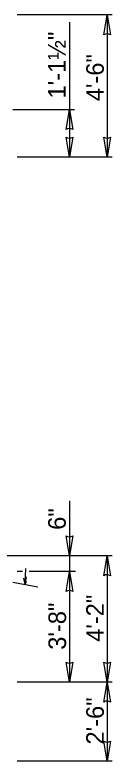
# Model space of a CAD drawing. Extents: x -30 to 76, y -31 to 50.
# Drawn here: x 29.22 to 29.99, y -20.83 to -14.93 of the extents above; entities that cross this region are included whole.
import ezdxf

# ---------------------------------------------------------------- set-up
doc = ezdxf.new("R2010")
doc.units = 0
for name, color, linetype in [('Default', 7, 'Continuous'), ('SH_Data', 7, 'Continuous'), ('XS_P_Finished_Grade', 7, 'Continuous')]:
    doc.layers.add(name, color=color, linetype=linetype)

msp = doc.modelspace()

# ---------------------------------------------------------------- linework, layer by layer
at = {"layer": 'Default'}
for p, q in [((29.9288, -15.0831), (29.9551, -14.9253)), ((29.9551, -14.9253), (29.9815, -15.0836)), ((29.9288, -15.0831), (29.9288, -15.0831)), ((29.9815, -15.0836), (29.9815, -15.0835)), ((29.6288, -15.8331), (29.6551, -15.6753)), ((29.6551, -15.6753), (29.6815, -15.8336)), ((29.6288, -15.8331), (29.6288, -15.8331)), ((29.6815, -15.8336), (29.6815, -15.8335)), ((29.6551, -16.0503), (29.6288, -15.892)), ((29.6288, -15.892), (29.6288, -15.8921)), ((29.6815, -15.8925), (29.6551, -16.0503)), ((29.6815, -15.8925), (29.6815, -15.8925)), ((29.9551, -16.0503), (29.9288, -15.892)), ((29.9288, -15.892), (29.9288, -15.8921)), ((29.9815, -15.8925), (29.9551, -16.0503)), ((29.9815, -15.8925), (29.9815, -15.8925)), ((29.6551, -19.2068), (29.6288, -19.0485)), ((29.6288, -19.0485), (29.6288, -19.0486)), ((29.6815, -19.049), (29.6551, -19.2068)), ((29.6815, -19.049), (29.6815, -19.049)), ((29.9288, -19.3645), (29.9551, -19.2068)), ((29.9551, -19.2068), (29.9815, -19.3651)), ((29.6288, -19.4895), (29.6551, -19.3318)), ((29.6551, -19.3318), (29.6815, -19.4901)), ((29.9288, -19.3645), (29.9288, -19.3645)), ((29.9815, -19.3651), (29.9815, -19.365)), ((29.6288, -19.4895), (29.6288, -19.4895)), ((29.6815, -19.4901), (29.6815, -19.49)), ((29.6551, -20.2068), (29.6288, -20.0486)), ((29.6288, -20.0486), (29.6288, -20.0487)), ((29.6815, -20.0491), (29.6551, -20.2068)), ((29.6815, -20.0491), (29.6815, -20.0491)), ((29.9551, -20.2068), (29.9288, -20.0486)), ((29.9288, -20.0486), (29.9288, -20.0487)), ((29.9815, -20.0491), (29.9551, -20.2068)), ((29.9815, -20.0491), (29.9815, -20.0491)), ((29.9288, -20.3646), (29.9551, -20.2068)), ((29.9551, -20.2068), (29.9815, -20.3651)), ((29.9288, -20.3646), (29.9288, -20.3646)), ((29.9815, -20.3651), (29.9815, -20.365)), ((29.9551, -20.8318), (29.9288, -20.6736)), ((29.9288, -20.6736), (29.9288, -20.6737)), ((29.9815, -20.6741), (29.9551, -20.8318)), ((29.9815, -20.6741), (29.9815, -20.6741))]:
    msp.add_line(p, q, dxfattribs=at)
for centre, start, end in [((29.9547, -15.1234), 56.178, 122.85877), ((29.6547, -15.8734), 56.178, 122.85877), ((29.6555, -15.8522), 236.178, 302.85877), ((29.9555, -15.8522), 236.178, 302.85877), ((29.6555, -19.0087), 236.178, 302.85877), ((29.9547, -19.4049), 56.178, 122.85877), ((29.6547, -19.5299), 56.178, 122.85877), ((29.6555, -20.0088), 236.178, 302.85877), ((29.9555, -20.0088), 236.178, 302.85877), ((29.9547, -20.4049), 56.178, 122.85877), ((29.9555, -20.6338), 236.178, 302.85877)]:
    msp.add_arc(centre, 0.048, start, end, dxfattribs=at)
at = {"layer": 'SH_Data'}
for p, q in [((29.9948, -14.9253), (29.2392, -14.9253)), ((29.9551, -14.9253), (29.9551, -16.0503)), ((29.6551, -14.9833), (29.6551, -15.6753)), ((29.6965, -15.6753), (29.2051, -15.6753)), ((29.6551, -15.6753), (29.6551, -16.0503)), ((29.9948, -16.0503), (29.2392, -16.0503)), ((29.6551, -18.772), (29.6551, -19.2068)), ((29.9948, -19.2068), (28.6646, -19.2068)), ((29.6551, -19.2068), (29.6551, -19.3318)), ((29.9551, -19.2068), (29.9551, -20.2068)), ((29.2833, -19.3318), (29.2392, -19.3318)), ((29.7031, -19.3318), (29.3351, -19.3318)), ((29.6551, -19.3318), (29.6551, -20.2068)), ((29.9948, -20.2068), (29.2392, -20.2068)), ((29.9551, -20.2068), (29.9551, -20.8318)), ((29.9948, -20.8318), (29.2392, -20.8318))]:
    msp.add_line(p, q, dxfattribs=at)
at = {"layer": 'XS_P_Finished_Grade'}
for p, q in [((29.3047, -19.434), (29.3095, -19.3078)), ((29.3047, -19.434), (29.3156, -19.3723)), ((29.2051, -19.4164), (29.4042, -19.4515)), ((29.3047, -19.434), (29.2942, -19.3848)), ((29.3047, -19.434), (29.3149, -19.4072))]:
    msp.add_line(p, q, dxfattribs=at)

# ---------------------------------------------------------------- texts
at = {"layer": 'SH_Data'}
for s, p in [('1\'-1½"', (29.6254, -15.5866)), ('4\'-6"', (29.9288, -15.6086)), ('6"', (29.6268, -19.0012)), ('4\'-2"', (29.9288, -19.8881)), ('3\'-8"', (29.6288, -19.9506)), ('2\'-6"', (29.9288, -20.7007))]:
    msp.add_text(s, height=0.14, rotation=90, dxfattribs=at).set_placement(p)

doc.saveas('drawing.dxf')
